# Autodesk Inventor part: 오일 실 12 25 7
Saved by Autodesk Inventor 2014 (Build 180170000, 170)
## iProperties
Created: 2026-08
Part Number: 오일 실 12 25 7
Material: 고무
Document SubType Name: Modeling
Designer: dg
Density: 0.93 g/cm^3
Appearance: 고무 - 검은색 - 버전 1.1
Mass: 1.26338 g
Surface Area: 20.8889 cm^2
Volume: 1.35847 cm^3
Author: jhkim
Description: 오일-실
Creation Date: 2026-07-31
Sending System: Autodesk Inventor 2027
Preprocessor: ST-DEVELOPER v20.1
Author: dg
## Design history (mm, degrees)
node "오일 실 12 25 71"
body "Solid1"
node "기준1"
